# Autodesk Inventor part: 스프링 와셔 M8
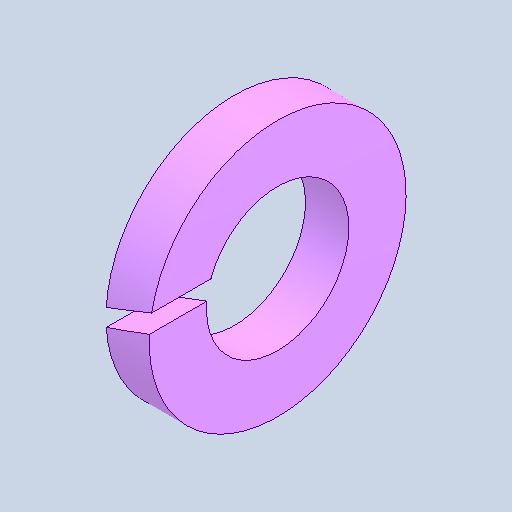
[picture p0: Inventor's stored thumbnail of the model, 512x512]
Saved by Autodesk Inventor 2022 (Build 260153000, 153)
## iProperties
Created: 2024-11
Part Number: 스프링 와셔 M8
Material: 강철, 연강
Description: 스프링 잠금 와셔
Document SubType Name: Modeling
Designer: PC-12
Density: 7.85 g/cm^3
Appearance: 기본값
Author: jhkim
Sending System: Autodesk Inventor 2025
Preprocessor: ST-DEVELOPER v20
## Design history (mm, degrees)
node "스프링 와셔 M81"
node "솔리드1"
body "Solid1"
